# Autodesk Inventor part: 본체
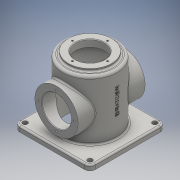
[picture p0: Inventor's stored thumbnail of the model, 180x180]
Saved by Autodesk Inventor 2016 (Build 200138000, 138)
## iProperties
Created: 2019-08
Part Number: 본체
Material: 일반
Document SubType Name: Modeling
Designer: user
Density: 1 g/cm^3
Appearance: 기본값
Author: user
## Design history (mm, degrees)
sketch "스케치1"
  geometry: L1 (-70, -70)-(70, -70); L2 (70, -70)-(70, 70); L3 (70, 70)-(-70, 70); L4 (-70, 70)-(-70, -70); L5 (-70, -70)-(70, 70); L6 (70, -70)-(-70, 70); 1 further point
  constraints: 12 end point, 2 midpoint, 2 parallel, 1 horizontal, 1 perpendicular
  dimensions: "d0" = 140 distance of L3.end L2.end; "d1" = 140 distance of L2.end L1.end
extrude "돌출1" new body sketch "스케치1" distance "d2" = 10; taper "d3" = 0 deg
sketch "스케치2"
  geometry: C1 r 50 at (0, 0); 1 further point
  constraints: 1 centre point, 1 coincident
  dimensions: "d4" = 100 diameter of C1
extrude "돌출2" join sketch "스케치2" distance "d5" = 110; taper "d6" = 0 deg
node "작업 평면1"
sketch "스케치3"
  geometry: L1 (70, 0)-(-70, 0) reference; C1 r 40 at (0, 60); 2 further points
  constraints: 1 centre point, 1 midpoint, 1 vertical alignment
  dimensions: "d8" = 80 diameter of C1; "d9" = 60 distance from line of L1 C1.centre
extrude "돌출3" join sketch "스케치3" stored distance "d10" = 110; taper "d11" = 0 deg
sketch "스케치4"
  geometry: C1 r 40 at (0, 0); 1 further point
  constraints: 1 centre point, 1 coincident
  dimensions: "d12" = 80 diameter of C1
extrude "돌출4" join sketch "스케치4" distance "d13" = 5; taper "d14" = 0 deg
hole "구멍1" diameter "d17" = 54; stored, may be unused: countersink angle "d21" = 90 deg, drill point angle "d23" = 118 deg; dims "d15" = 10, "d16" = 10, "d18" = 6, "d19" = 4, "d20" = 2, "d22" = 8
hole "구멍2" diameter "d26" = 90; stored, may be unused: countersink angle "d30" = 90 deg, drill point angle "d32" = 0 deg; dims "d27" = 6, "d28" = 4, "d29" = 2, "d31" = 112, "d98" = 10, "d99" = 10
hole "구멍3" diameter "d35" = 54; stored, may be unused: countersink angle "d39" = 90 deg, drill point angle "d41" = 118 deg; dims "d33" = 10, "d34" = 10, "d36" = 6, "d37" = 4, "d38" = 2, "d40" = 112
sketch "스케치5"
  geometry: L1 (70, -50)-(70, -60) reference; L2 (70, -60)-(-70, -60) reference; L3 (-70, -60)-(-70, -50) reference; L4 (-70, -50)-(70, -50) reference; C1 r 27 at (0, 0) reference; C2 r 40 at (0, 0) reference; 2 further points
  constraints: 1 vertical alignment
  dimensions: "d43" = 32.5 distance of C1.centre point (0, 32.5)
hole "구멍4" sketch "스케치5" at (0, 32.5) diameter "d44" = 3.242; stored, may be unused: countersink angle "d48" = 90 deg, drill point angle "d50" = 118 deg; dims "d45" = 8, "d46" = 4, "d47" = 2, "d49" = 10
sketch "스케치6"
  geometry: 2 further points
  constraints: 1 vertical alignment
  dimensions: "d54" = 32.5 distance of point (0, 0) point (0, -32.5)
hole "구멍5" sketch "스케치6" at (0, -32.5) diameter "d55" = 3.242; stored, may be unused: countersink angle "d59" = 90 deg, drill point angle "d61" = 118 deg; dims "d56" = 8, "d57" = 4, "d58" = 2, "d60" = 10
fillet "모깎기1" dims "d65" = 10
hole "구멍6" diameter "d68" = 9; stored, may be unused: countersink angle "d72" = 90 deg, drill point angle "d74" = 0 deg; dims "d66" = 10, "d67" = 10, "d69" = 8, "d70" = 4, "d71" = 2, "d73" = 10
fillet "모깎기2" dims "d81" = 3
fillet "모깎기3" dims "d82" = 3
fillet "모깎기4" dims "d83" = 3
fillet "모깎기5" dims "d84" = 3
fillet "모깎기6" dims "d85" = 3
fillet "모깎기7" dims "d86" = 5
chamfer "모따기1" distance "d87" = 1; stored, may be unused: second distance "d88" = 2, angle "d89" = 45 deg
chamfer "모따기2" distance "d90" = 1; stored, may be unused: second distance "d91" = 2, angle "d92" = 45 deg
fillet "모깎기8" dims "d93" = 3
node "작업 평면2"
sketch "스케치7" dims "d0" = 140, "d1" = 140
  geometry: L1 (-60, 0)-(60, 0) reference; 3 further points
  constraints: 1 midpoint, 1 vertical alignment, 1 other
  dimensions: "d95" = 70 distance from line of L1 point (0, 70)
feature "엠보싱1" sketch "스케치7" dims "d96" = 0.5, "d97" = 0
node "솔리드1"
mirror "대칭1"
pattern_circular "원형 패턴1" dims angle "d52" = 360 deg
mirror "대칭2"
pattern_circular "원형 패턴2" dims angle "d63" = 360 deg
pattern_linear "직사각형 패턴1" dims "d77" = 120
node "절단 모서리 투영1"
other parameters: "d7" = -62, "d94" = 55
